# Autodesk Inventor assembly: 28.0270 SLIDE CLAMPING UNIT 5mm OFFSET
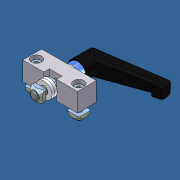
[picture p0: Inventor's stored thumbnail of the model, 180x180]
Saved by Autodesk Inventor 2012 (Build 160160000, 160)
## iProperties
Created: 2007-06
Part Number: 28.0270 SLIDE CLAMPING UNIT 5mm OFFSET
Document SubType Name: Assembly
Designer: Andy Moles
Vendor: V
Author: Andy Moles
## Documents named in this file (8)
- C:\Andys Backup Data\ANDY'S INVENTOR\INVENTOR LIBRARIES\PARTS LIBRARY\COMPONENTS LR\SUBCOMPONENTS\28.0270 SLIDE CLAMPING UNIT 5mm OFFSET.iam
- C:\Andys Backup Data\ANDY'S INVENTOR\INVENTOR LIBRARIES\PARTS LIBRARY\COMPONENTS LR\SUBCOMPONENTS\28.0270 SLIDE CLAMPING UNIT AL BLOCK.ipt
- C:\Andys Backup Data\ANDY'S INVENTOR\INVENTOR LIBRARIES\PARTS LIBRARY\FASTENING ELEMENTS\SCREWS CAP\21.1242 M6X25.ipt
- C:\Andys Backup Data\ANDY'S INVENTOR\INVENTOR LIBRARIES\PARTS LIBRARY\FASTENING ELEMENTS\NUTS\21.1330 M6 SQUARE NUT.ipt
- C:\Andys Backup Data\ANDY'S INVENTOR\INVENTOR LIBRARIES\PARTS LIBRARY\FASTENING ELEMENTS\WASHERS\WASHER M8 PLASTIC 17mm OD.ipt
- C:\Andys Backup Data\ANDY'S INVENTOR\INVENTOR LIBRARIES\PARTS LIBRARY\COMPONENTS LR\SUBCOMPONENTS\28.0270 SLIDE CLAMPING UNIT HANDLE.ipt
- C:\Andys Backup Data\ANDY'S INVENTOR\INVENTOR LIBRARIES\PARTS LIBRARY\COMPONENTS LR\SUBCOMPONENTS\28.0270 THREADED STUD.ipt
- C:\Andys Backup Data\ANDY'S INVENTOR\INVENTOR LIBRARIES\PARTS LIBRARY\FASTENING ELEMENTS\NUTS\21.1351 M8 SQUARE NUT.ipt
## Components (12 placed, 7 different names)
1. 28.0270 SLIDE CLAMPING UNIT AL BLOCK:1 — Insert:1, Insert:2, Insert:3, Insert:4, Insert:5, Angle:1, Angle:2
2. 21.1242 M6 x 25:1 — Insert:1
3. 21.1242 M6 x 25:2 — Insert:2
4. 21.1330 M6 SQUARE NUT:1 — Insert:4
5. 21.1330 M6 SQUARE NUT:2 — Insert:3
6. WASHER M8 PLASTIC 17mm OD:1 — Insert:5, Insert:12, Mate:7
7. WASHER M8 PLASTIC 17mm OD:3 — Mate:2, Insert:10, Insert:13
8. 28.0270 SLIDE CLAMPING UNIT HANDLE:1 — Insert:12, Mate:8
9. 28.0270 THREADED STUD:1 — Mate:1, Mate:5, Mate:7, Mate:8
10. 21.1351 M8 SQUARE NUT:1 — Mate:1, Angle:1, Mate:6
11. 21.1351 M8 SQUARE NUT:2 — Insert:10, Angle:2
12. WASHER M8 PLASTIC 17mm OD:4 — Insert:13, Mate:5, Mate:6
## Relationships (16: Insert 8, Mate 6, Angle 2)
- Insert:1: 28.0270 SLIDE CLAMPING UNIT AL BLOCK:1 ↔ 21.1242 M6 x 25:1
- Insert:2: 28.0270 SLIDE CLAMPING UNIT AL BLOCK:1 ↔ 21.1242 M6 x 25:2
- Insert:3: 28.0270 SLIDE CLAMPING UNIT AL BLOCK:1 ↔ 21.1330 M6 SQUARE NUT:2
- Insert:4: 28.0270 SLIDE CLAMPING UNIT AL BLOCK:1 ↔ 21.1330 M6 SQUARE NUT:1
- Insert:5: 28.0270 SLIDE CLAMPING UNIT AL BLOCK:1 ↔ WASHER M8 PLASTIC 17mm OD:1
- Mate:1: 28.0270 THREADED STUD:1 ↔ 21.1351 M8 SQUARE NUT:1
- Mate:2: WASHER M8 PLASTIC 17mm OD:3
- Insert:10: WASHER M8 PLASTIC 17mm OD:3 ↔ 21.1351 M8 SQUARE NUT:2
- Insert:12: WASHER M8 PLASTIC 17mm OD:1 ↔ 28.0270 SLIDE CLAMPING UNIT HANDLE:1
- Angle:1: 28.0270 SLIDE CLAMPING UNIT AL BLOCK:1 ↔ 21.1351 M8 SQUARE NUT:1
- Insert:13: WASHER M8 PLASTIC 17mm OD:3 ↔ WASHER M8 PLASTIC 17mm OD:4
- Angle:2: 28.0270 SLIDE CLAMPING UNIT AL BLOCK:1 ↔ 21.1351 M8 SQUARE NUT:2
- Mate:5: 28.0270 THREADED STUD:1 ↔ WASHER M8 PLASTIC 17mm OD:4
- Mate:6: 21.1351 M8 SQUARE NUT:1 ↔ WASHER M8 PLASTIC 17mm OD:4
- Mate:7: WASHER M8 PLASTIC 17mm OD:1 ↔ 28.0270 THREADED STUD:1
- Mate:8: 28.0270 SLIDE CLAMPING UNIT HANDLE:1 ↔ 28.0270 THREADED STUD:1
